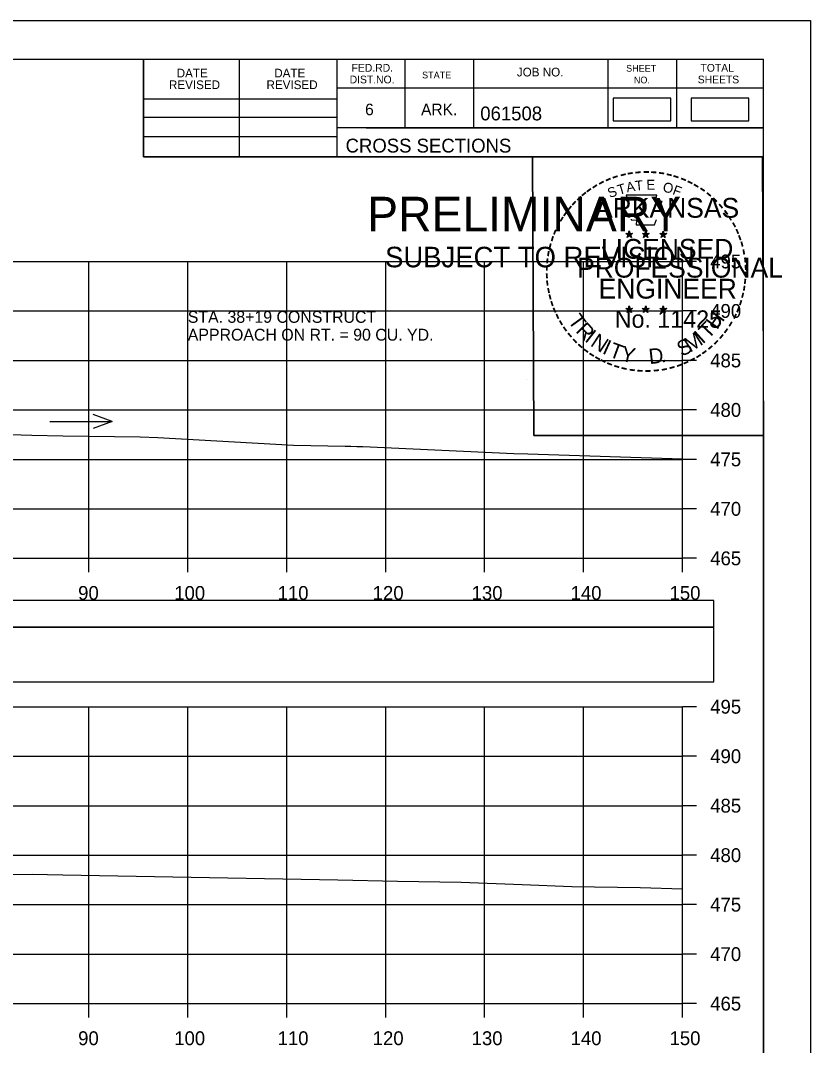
# Model space of a CAD drawing. Extents: x 1371057 to 1372761, y 380005 to 390517.
# Drawn here: x 1371644 to 1371723.8, y 381181.5 to 381285.1 of the extents above; entities that cross this region are included whole.
import ezdxf

# ---------------------------------------------------------------- set-up
doc = ezdxf.new("R2010")
doc.units = 0
for name, color, linetype in [('R_Axis', 7, 'Continuous'), ('R_Axis Annot', 7, 'Continuous'), ('R_Border', 7, 'Continuous'), ('R_Border PE', 7, 'Continuous'), ('R_Border Prem', 7, 'Continuous'), ('R_Detour', 7, 'Continuous'), ('R_Dimension', 7, 'Continuous'), ('R_Exist Surface', 7, 'Continuous'), ('R_Grid', 7, 'Continuous'), ('R_No Plot', 7, 'Continuous'), ('R_Water Annot', 7, 'Continuous')]:
    doc.layers.add(name, color=color, linetype=linetype)

msp = doc.modelspace()

# ---------------------------------------------------------------- linework, layer by layer
at = {"layer": 'R_Axis'}
for p, q in [((1371710.87, 381230.75), (1371710.87, 381260.75)), ((1371712.27, 381260.75), (1371710.87, 381260.75)), ((1371712.27, 381255.75), (1371710.87, 381255.75)), ((1371712.27, 381250.75), (1371710.87, 381250.75)), ((1371712.27, 381245.75), (1371710.87, 381245.75)), ((1371712.27, 381240.75), (1371710.87, 381240.75)), ((1371712.27, 381235.75), (1371710.87, 381235.75)), ((1371410.87, 381230.75), (1371710.87, 381230.75)), ((1371650.87, 381229.35), (1371650.87, 381230.75)), ((1371660.87, 381229.35), (1371660.87, 381230.75)), ((1371670.87, 381229.35), (1371670.87, 381230.75)), ((1371680.87, 381229.35), (1371680.87, 381230.75)), ((1371690.87, 381229.35), (1371690.87, 381230.75)), ((1371700.87, 381229.35), (1371700.87, 381230.75)), ((1371710.87, 381229.35), (1371710.87, 381230.75)), ((1371712.27, 381230.75), (1371710.87, 381230.75)), ((1371710.87, 381185.75), (1371710.87, 381215.75)), ((1371712.27, 381215.75), (1371710.87, 381215.75)), ((1371712.27, 381210.75), (1371710.87, 381210.75)), ((1371712.27, 381205.75), (1371710.87, 381205.75)), ((1371712.27, 381200.75), (1371710.87, 381200.75)), ((1371712.27, 381195.75), (1371710.87, 381195.75)), ((1371712.27, 381190.75), (1371710.87, 381190.75)), ((1371410.87, 381185.75), (1371710.87, 381185.75)), ((1371650.87, 381184.35), (1371650.87, 381185.75)), ((1371660.87, 381184.35), (1371660.87, 381185.75)), ((1371670.87, 381184.35), (1371670.87, 381185.75)), ((1371680.87, 381184.35), (1371680.87, 381185.75)), ((1371690.87, 381184.35), (1371690.87, 381185.75)), ((1371700.87, 381184.35), (1371700.87, 381185.75)), ((1371710.87, 381184.35), (1371710.87, 381185.75)), ((1371712.27, 381185.75), (1371710.87, 381185.75))]:
    msp.add_line(p, q, dxfattribs=at)
at = {"layer": 'R_Border'}
for p, q in [((1371402.87, 381281.21), (1371719.05, 381281.21)), ((1371656.41, 381271.33), (1371656.41, 381281.21)), ((1371666.09, 381271.33), (1371666.09, 381281.21)), ((1371675.95, 381281.21), (1371675.95, 381271.33)), ((1371682.79, 381281.21), (1371682.79, 381274.27)), ((1371689.73, 381281.21), (1371689.73, 381274.27)), ((1371703.31, 381281.21), (1371703.31, 381274.27)), ((1371710.25, 381281.21), (1371710.25, 381274.27)), ((1371719.05, 381075.75), (1371719.05, 381281.21)), ((1371719.05, 381278.27), (1371675.95, 381278.27)), ((1371719.05, 381278.29), (1371719.05, 381278.29)), ((1371656.41, 381277.19), (1371675.95, 381277.19)), ((1371656.41, 381275.33), (1371675.95, 381275.33)), ((1371719.05, 381274.27), (1371675.95, 381274.27)), ((1371678.91, 381274.27), (1371719.05, 381274.27)), ((1371656.41, 381273.39), (1371675.95, 381273.39)), ((1371719.05, 381271.33), (1371656.41, 381271.33))]:
    msp.add_line(p, q, dxfattribs=at)
at = {"layer": 'R_Border PE'}
for p, q in [((1371705.14, 381263.58), (1371705.49, 381263.47)), ((1371705.14, 381263.58), (1371705.39, 381263.54)), ((1371705.14, 381263.58), (1371705.37, 381263.46)), ((1371705.49, 381263.84), (1371705.45, 381263.59)), ((1371705.49, 381263.47), (1371705.49, 381263.84)), ((1371705.49, 381263.84), (1371705.54, 381263.59)), ((1371705.83, 381263.58), (1371705.49, 381263.47)), ((1371705.83, 381263.58), (1371705.55, 381263.54)), ((1371705.83, 381263.58), (1371705.63, 381263.48)), ((1371706.81, 381263.58), (1371707.16, 381263.47)), ((1371706.81, 381263.58), (1371707.06, 381263.54)), ((1371706.81, 381263.58), (1371707.04, 381263.46)), ((1371707.16, 381263.84), (1371707.12, 381263.59)), ((1371707.16, 381263.47), (1371707.16, 381263.84)), ((1371707.16, 381263.84), (1371707.21, 381263.59)), ((1371707.5, 381263.58), (1371707.16, 381263.47)), ((1371707.5, 381263.58), (1371707.22, 381263.54)), ((1371707.5, 381263.58), (1371707.3, 381263.48)), ((1371708.57, 381263.57), (1371708.92, 381263.46)), ((1371708.57, 381263.57), (1371708.82, 381263.53)), ((1371708.57, 381263.57), (1371708.81, 381263.45)), ((1371708.92, 381263.83), (1371708.88, 381263.57)), ((1371708.92, 381263.46), (1371708.92, 381263.83)), ((1371708.92, 381263.83), (1371708.97, 381263.58)), ((1371709.27, 381263.57), (1371708.92, 381263.46)), ((1371709.27, 381263.57), (1371708.98, 381263.52)), ((1371709.27, 381263.57), (1371709.06, 381263.47)), ((1371705.27, 381263.18), (1371705.49, 381263.47)), ((1371705.27, 381263.18), (1371705.4, 381263.42)), ((1371705.27, 381263.18), (1371705.48, 381263.39)), ((1371705.7, 381263.18), (1371705.48, 381263.39)), ((1371705.7, 381263.18), (1371705.49, 381263.47)), ((1371705.7, 381263.18), (1371705.56, 381263.47)), ((1371706.94, 381263.18), (1371707.16, 381263.47)), ((1371706.94, 381263.18), (1371707.07, 381263.42)), ((1371706.94, 381263.18), (1371707.15, 381263.39)), ((1371707.37, 381263.18), (1371707.15, 381263.39)), ((1371707.37, 381263.18), (1371707.16, 381263.47)), ((1371707.37, 381263.18), (1371707.23, 381263.47)), ((1371708.7, 381263.16), (1371708.92, 381263.46)), ((1371708.7, 381263.16), (1371708.83, 381263.41)), ((1371708.7, 381263.16), (1371708.92, 381263.38)), ((1371709.13, 381263.16), (1371708.92, 381263.46)), ((1371709.13, 381263.16), (1371708.92, 381263.38)), ((1371709.13, 381263.16), (1371709, 381263.46)), ((1371705.48, 381256.27), (1371705.44, 381256.01)), ((1371705.48, 381255.9), (1371705.48, 381256.27)), ((1371705.48, 381256.27), (1371705.53, 381256.02)), ((1371707.15, 381256.27), (1371707.11, 381256.01)), ((1371707.15, 381255.9), (1371707.15, 381256.27)), ((1371707.15, 381256.27), (1371707.2, 381256.02)), ((1371708.92, 381256.26), (1371708.88, 381256)), ((1371708.92, 381255.89), (1371708.92, 381256.26)), ((1371708.92, 381256.26), (1371708.97, 381256.01)), ((1371705.13, 381256.01), (1371705.48, 381255.9)), ((1371705.13, 381256.01), (1371705.39, 381255.97)), ((1371705.13, 381256.01), (1371705.37, 381255.89)), ((1371705.27, 381255.6), (1371705.48, 381255.9)), ((1371705.27, 381255.6), (1371705.39, 381255.85)), ((1371705.27, 381255.6), (1371705.48, 381255.82)), ((1371705.83, 381256.01), (1371705.48, 381255.9)), ((1371705.7, 381255.6), (1371705.48, 381255.9)), ((1371705.7, 381255.6), (1371705.48, 381255.82)), ((1371705.83, 381256.01), (1371705.54, 381255.96)), ((1371705.7, 381255.6), (1371705.56, 381255.89)), ((1371705.83, 381256.01), (1371705.63, 381255.91)), ((1371706.8, 381256.01), (1371707.15, 381255.9)), ((1371706.8, 381256.01), (1371707.06, 381255.97)), ((1371706.8, 381256.01), (1371707.04, 381255.89)), ((1371706.94, 381255.6), (1371707.15, 381255.9)), ((1371706.94, 381255.6), (1371707.06, 381255.85)), ((1371706.94, 381255.6), (1371707.15, 381255.82)), ((1371707.5, 381256.01), (1371707.15, 381255.9)), ((1371707.36, 381255.6), (1371707.15, 381255.9)), ((1371707.36, 381255.6), (1371707.15, 381255.82)), ((1371707.5, 381256.01), (1371707.21, 381255.96)), ((1371707.36, 381255.6), (1371707.23, 381255.89)), ((1371707.5, 381256.01), (1371707.29, 381255.91)), ((1371708.57, 381256), (1371708.92, 381255.89)), ((1371708.57, 381256), (1371708.82, 381255.96)), ((1371708.57, 381256), (1371708.81, 381255.88)), ((1371708.7, 381255.59), (1371708.92, 381255.89)), ((1371708.7, 381255.59), (1371708.83, 381255.84)), ((1371708.7, 381255.59), (1371708.92, 381255.81)), ((1371709.27, 381256), (1371708.92, 381255.89)), ((1371709.13, 381255.59), (1371708.92, 381255.89)), ((1371709.13, 381255.59), (1371708.92, 381255.81)), ((1371709.27, 381256), (1371708.98, 381255.95)), ((1371709.13, 381255.59), (1371708.99, 381255.88)), ((1371709.27, 381256), (1371709.06, 381255.9))]:
    msp.add_line(p, q, dxfattribs=at)
for points in [[(1371705.18, 381267.46), (1371705.45, 381266.64)], [(1371708.69, 381266.54), (1371708.83, 381266.82), (1371708.15, 381266.8), (1371708.29, 381267.46), (1371705.18, 381267.46)], [(1371705.67, 381265.04), (1371705.67, 381264.95), (1371706.23, 381264.93), (1371706.18, 381264.46), (1371708.05, 381264.46), (1371708.25, 381265)], [(1371705.49, 381263.84), (1371705.7, 381263.18), (1371705.14, 381263.58), (1371705.83, 381263.58), (1371705.27, 381263.18), (1371705.49, 381263.84)], [(1371707.16, 381263.84), (1371707.37, 381263.18), (1371706.81, 381263.58), (1371707.5, 381263.58), (1371706.94, 381263.18), (1371707.16, 381263.84)], [(1371708.92, 381263.83), (1371709.13, 381263.16), (1371708.57, 381263.57), (1371709.27, 381263.57), (1371708.7, 381263.16), (1371708.92, 381263.83)], [(1371705.48, 381256.27), (1371705.7, 381255.6), (1371705.13, 381256.01), (1371705.83, 381256.01), (1371705.27, 381255.6), (1371705.48, 381256.27)], [(1371707.15, 381256.27), (1371707.36, 381255.6), (1371706.8, 381256.01), (1371707.5, 381256.01), (1371706.94, 381255.6), (1371707.15, 381256.27)], [(1371708.92, 381256.26), (1371709.13, 381255.59), (1371708.57, 381256), (1371709.27, 381256), (1371708.7, 381255.59), (1371708.92, 381256.26)]]:
    msp.add_lwpolyline(points, dxfattribs=at)
for centre, radius in [((1371705.49, 381263.47), 0.172), ((1371705.49, 381263.47), 0.145), ((1371705.49, 381263.47), 0.116), ((1371705.49, 381263.47), 0.0991), ((1371705.49, 381263.47), 0.0747), ((1371705.49, 381263.47), 0.0495), ((1371705.49, 381263.47), 0.0296), ((1371707.16, 381263.47), 0.172), ((1371707.16, 381263.47), 0.145), ((1371707.16, 381263.47), 0.116), ((1371707.16, 381263.47), 0.0991), ((1371707.16, 381263.47), 0.0747), ((1371707.16, 381263.47), 0.0495), ((1371707.16, 381263.47), 0.0296), ((1371708.92, 381263.46), 0.172), ((1371708.92, 381263.46), 0.145), ((1371708.92, 381263.46), 0.116), ((1371708.92, 381263.46), 0.0991), ((1371708.92, 381263.46), 0.0747), ((1371708.92, 381263.46), 0.0495), ((1371708.92, 381263.46), 0.0296), ((1371705.48, 381255.9), 0.172), ((1371705.48, 381255.9), 0.145), ((1371705.48, 381255.9), 0.116), ((1371705.48, 381255.9), 0.0991), ((1371705.48, 381255.9), 0.0747), ((1371705.48, 381255.9), 0.0495), ((1371705.48, 381255.9), 0.0296), ((1371707.15, 381255.9), 0.172), ((1371707.15, 381255.9), 0.145), ((1371707.15, 381255.9), 0.116), ((1371707.15, 381255.9), 0.0991), ((1371707.15, 381255.9), 0.0747), ((1371707.15, 381255.9), 0.0495), ((1371707.15, 381255.9), 0.0296), ((1371708.92, 381255.89), 0.172), ((1371708.92, 381255.89), 0.145), ((1371708.92, 381255.89), 0.116), ((1371708.92, 381255.89), 0.0991), ((1371708.92, 381255.89), 0.0747), ((1371708.92, 381255.89), 0.0495), ((1371708.92, 381255.89), 0.0296)]:
    msp.add_circle(centre, radius, dxfattribs=at)
at = {"layer": 'R_Detour'}
msp.add_lwpolyline([(1371407.72, 381223.8), (1371714.03, 381223.8), (1371714.03, 381226.5), (1371407.72, 381226.5)], close=True, dxfattribs=at)
at = {"layer": 'R_Dimension'}
for points in [[(1371703.87, 381274.96), (1371709.7, 381274.96), (1371709.7, 381277.27), (1371703.87, 381277.27)], [(1371711.74, 381274.96), (1371717.57, 381274.96), (1371717.57, 381277.27), (1371711.74, 381277.27)], [(1371407.72, 381218.27), (1371714.03, 381218.27), (1371714.03, 381223.8), (1371407.72, 381223.8)]]:
    msp.add_lwpolyline(points, close=True, dxfattribs=at)
at = {"layer": 'R_Exist Surface'}
for points in [[(1371641.92, 381243.3), (1371645.1, 381243.19), (1371648.24, 381243.12), (1371656.05, 381243.04), (1371657.85, 381242.96), (1371671.57, 381242.18), (1371676.78, 381242.09), (1371677.35, 381242.07), (1371677.96, 381242.06), (1371678.55, 381242.04), (1371693.82, 381241.34), (1371695.24, 381241.32), (1371710.87, 381240.82)], [(1371634.78, 381198.78), (1371645.15, 381198.83), (1371648.24, 381198.76), (1371676.03, 381198.27), (1371682.05, 381198.12), (1371688.49, 381198.03), (1371694.66, 381197.8), (1371699.68, 381197.57), (1371706.6, 381197.49), (1371710.87, 381197.36)]]:
    msp.add_lwpolyline(points, dxfattribs=at)
at = {"layer": 'R_Grid'}
for p, q in [((1371410.87, 381260.75), (1371710.87, 381260.75)), ((1371650.87, 381230.75), (1371650.87, 381260.75)), ((1371660.87, 381230.75), (1371660.87, 381260.75)), ((1371670.87, 381230.75), (1371670.87, 381260.75)), ((1371680.87, 381230.75), (1371680.87, 381260.75)), ((1371690.87, 381230.75), (1371690.87, 381260.75)), ((1371700.87, 381230.75), (1371700.87, 381260.75)), ((1371710.87, 381230.75), (1371710.87, 381260.75)), ((1371410.87, 381255.75), (1371710.87, 381255.75)), ((1371410.87, 381250.75), (1371710.87, 381250.75)), ((1371410.87, 381245.75), (1371710.87, 381245.75)), ((1371410.87, 381240.75), (1371710.87, 381240.75)), ((1371410.87, 381235.75), (1371710.87, 381235.75)), ((1371410.87, 381230.75), (1371710.87, 381230.75)), ((1371410.87, 381215.75), (1371710.87, 381215.75)), ((1371650.87, 381185.75), (1371650.87, 381215.75)), ((1371660.87, 381185.75), (1371660.87, 381215.75)), ((1371670.87, 381185.75), (1371670.87, 381215.75)), ((1371680.87, 381185.75), (1371680.87, 381215.75)), ((1371690.87, 381185.75), (1371690.87, 381215.75)), ((1371700.87, 381185.75), (1371700.87, 381215.75)), ((1371710.87, 381185.75), (1371710.87, 381215.75)), ((1371410.87, 381210.75), (1371710.87, 381210.75)), ((1371410.87, 381205.75), (1371710.87, 381205.75)), ((1371410.87, 381200.75), (1371710.87, 381200.75)), ((1371410.87, 381195.75), (1371710.87, 381195.75)), ((1371410.87, 381190.75), (1371710.87, 381190.75)), ((1371410.87, 381185.75), (1371710.87, 381185.75))]:
    msp.add_line(p, q, dxfattribs=at)
at = {"layer": 'R_No Plot'}
for p, q in [((1371390.47, 381285.1), (1371723.8, 381285.1)), ((1371695.09, 381248.87), (1371695.09, 381248.87))]:
    msp.add_line(p, q, dxfattribs=at)
for points in [[(1371390.46, 381285.1), (1371723.8, 381285.1), (1371723.8, 381071.77), (1371390.46, 381071.77)], [(1371636.79, 381281.21), (1371656.41, 381281.21), (1371656.41, 381271.33), (1371672.52, 381271.33), (1371695.72, 381271.33), (1371695.84, 381243.17), (1371719.05, 381243.17), (1371719.05, 381075.75), (1371402.87, 381075.75), (1371402.87, 381281.21)], [(1371695.72, 381271.33), (1371718.93, 381271.33), (1371719.05, 381243.17), (1371695.84, 381243.17)]]:
    msp.add_lwpolyline(points, close=True, dxfattribs=at)
at = {"layer": 'R_Water Annot'}
for p, q in [((1371653.22, 381244.57), (1371651.3, 381245.27)), ((1371646.94, 381244.57), (1371653.22, 381244.57)), ((1371653.22, 381244.57), (1371651.3, 381243.87))]:
    msp.add_line(p, q, dxfattribs=at)

# ---------------------------------------------------------------- texts
at = {"layer": 'R_Axis Annot'}
for s, p in [('495', (1371713.67, 381260.05)), ('490', (1371713.67, 381255.05)), ('485', (1371713.67, 381250.05)), ('480', (1371713.67, 381245.05)), ('475', (1371713.67, 381240.05)), ('470', (1371713.67, 381235.05)), ('465', (1371713.67, 381230.05)), ('90', (1371649.79, 381226.55)), ('100', (1371659.5, 381226.55)), ('110', (1371669.95, 381226.55)), ('120', (1371679.56, 381226.55)), ('130', (1371689.56, 381226.55)), ('140', (1371699.56, 381226.55)), ('150', (1371709.56, 381226.55)), ('495', (1371713.67, 381215.05)), ('490', (1371713.67, 381210.05)), ('485', (1371713.67, 381205.05)), ('480', (1371713.67, 381200.05)), ('475', (1371713.67, 381195.05)), ('470', (1371713.67, 381190.05)), ('465', (1371713.67, 381185.05)), ('90', (1371649.79, 381181.55)), ('100', (1371659.5, 381181.55)), ('110', (1371669.95, 381181.55)), ('120', (1371679.56, 381181.55)), ('130', (1371689.56, 381181.55)), ('140', (1371699.56, 381181.55)), ('150', (1371709.56, 381181.55))]:
    msp.add_text(s, height=1.4, dxfattribs=at).set_placement(p)
at = {"layer": 'R_Border'}
for s, height, p in [('DATE', 0.879, (1371659.75, 381279.35)), ('DATE', 0.879, (1371669.61, 381279.35)), ('FED.RD.', 0.782, (1371677.43, 381279.93)), ('JOB NO.', 0.879, (1371694.13, 381279.45)), ('SHEET', 0.684, (1371705.17, 381279.93)), ('TOTAL', 0.782, (1371712.69, 381279.93)), ('REVISED', 0.879, (1371658.97, 381278.17)), ('REVISED', 0.879, (1371668.83, 381278.17)), ('DIST.NO.', 0.782, (1371677.23, 381278.75)), ('STATE', 0.684, (1371684.55, 381279.25)), ('NO.', 0.684, (1371705.95, 381278.75)), ('SHEETS', 0.782, (1371712.41, 381278.75)), ('6', 1.17, (1371678.79, 381275.53)), ('ARK.', 1.172, (1371684.45, 381275.53)), ('061508', 1.4, (1371690.43, 381275.01)), ('CROSS SECTIONS', 1.4, (1371676.82, 381271.76))]:
    msp.add_text(s, height=height, rotation=360, dxfattribs=at).set_placement(p)
at = {"layer": 'R_Border PE'}
for s, height, rotation, p in [('-', 1.6, 10.2193, (1371705.35, 381268.99)), ('-', 1.6, 5.8968, (1371706.08, 381269.1)), ('-', 1.6, 0.1862, (1371706.86, 381269.17)), ('-', 1.6, 357.743, (1371707.58, 381269.16)), ('-', 1.6, 352.1617, (1371708.32, 381269.11)), ('-', 1.6, 28.7918, (1371702.66, 381268)), ('-', 1.6, 24.3072, (1371703.29, 381268.32)), ('-', 1.6, 19.1761, (1371703.93, 381268.59)), ('-', 1.6, 13.6301, (1371704.68, 381268.83)), ('A', 1, 11.2132, (1371705.27, 381267.72)), ('T', 1, 6.0228, (1371706.12, 381267.89)), ('E', 1, 0.8323, (1371707.23, 381268)), ('O', 1, 350.4515, (1371708.83, 381267.79)), ('-', 1.6, 347.2049, (1371709.04, 381268.99)), ('-', 1.6, 342.3362, (1371709.68, 381268.84)), ('-', 1.6, 337.8551, (1371710.41, 381268.61)), ('-', 1.6, 334.1211, (1371711.04, 381268.34)), ('-', 1.6, 38.9507, (1371701.01, 381266.86)), ('-', 1.6, 36.2317, (1371701.48, 381267.24)), ('-', 1.6, 34.0636, (1371702.06, 381267.63)), ('S', 1, 21.594, (1371703.53, 381267.14)), ('T', 1, 16.4036, (1371704.45, 381267.47)), ('F', 1, 340.0707, (1371709.79, 381267.56)), ('-', 1.6, 329.6409, (1371711.62, 381268.06)), ('-', 1.6, 325.8627, (1371712.26, 381267.7)), ('-', 1.6, 320.5297, (1371712.87, 381267.27)), ('-', 1.6, 48.423, (1371700.13, 381265.97)), ('-', 1.6, 42.9622, (1371700.58, 381266.44)), ('ARKANSAS', 2, 360, (1371702.03, 381265.17)), ('-', 1.6, 315.5786, (1371713.47, 381266.78)), ('-', 1.6, 309.8797, (1371714.04, 381266.23)), ('-', 1.6, 54.2325, (1371699.31, 381264.91)), ('-', 1.6, 50.6142, (1371699.72, 381265.48)), ('-', 1.6, 306.6522, (1371714.57, 381265.63)), ('-', 1.6, 62.8713, (1371698.67, 381263.77)), ('-', 1.6, 58.0706, (1371698.99, 381264.39)), ('-', 1.4, 303.6753, (1371715.05, 381265.06)), ('-', 1.6, 299.6684, (1371715.37, 381264.46)), ('-', 1.6, 67.7743, (1371698.41, 381263.16)), ('-', 1.6, 294.6628, (1371715.7, 381263.85)), ('-', 1.6, 75.461, (1371698, 381261.82)), ('-', 1.6, 72.3945, (1371698.2, 381262.53)), ('LICENSED', 2, 360, (1371702.63, 381261.03)), ('DWB', 0.01, 360, (1371705.47, 381263.47)), ('DWB', 0.01, 360, (1371707.14, 381263.47)), ('DWB', 0.01, 360, (1371708.91, 381263.46)), ('-', 1.6, 290.5728, (1371715.95, 381263.27)), ('-', 1.6, 285.1233, (1371716.19, 381262.69)), ('-', 1.6, 81.2013, (1371697.87, 381261.1)), ('-', 1.6, 280.5493, (1371716.39, 381261.95)), ('-', 1.6, 85.1863, (1371697.79, 381260.41)), ('PROFESSIONAL', 2, 360, (1371700.21, 381259.12)), ('-', 1.6, 276.5962, (1371716.55, 381261.18)), ('-', 1.6, 274.3301, (1371716.61, 381260.46)), ('-', 1.6, 94.1959, (1371697.8, 381258.99)), ('-', 1.6, 89.0622, (1371697.77, 381259.71)), ('-', 1.6, 269.9407, (1371716.64, 381259.82)), ('-', 1.6, 98.9479, (1371697.87, 381258.32)), ('ENGINEER', 2, 360, (1371702.39, 381257)), ('-', 1.6, 260.9953, (1371716.55, 381258.5)), ('-', 1.6, 263.5172, (1371716.62, 381259.16)), ('-', 1.6, 101.7149, (1371698.01, 381257.59)), ('-', 1.6, 105.4578, (1371698.17, 381256.99)), ('-', 1.6, 255.7626, (1371716.44, 381257.83)), ('-', 1.6, 109.0874, (1371698.38, 381256.36)), ('-', 1.6, 252.8681, (1371716.26, 381257.11)), ('-', 1.6, 114.0643, (1371698.64, 381255.76)), ('-', 1.6, 115.7289, (1371698.94, 381255.15)), ('T', 1.54, 306.0406, (1371699.24, 381254.74)), ('No. 11425', 1.757, 360, (1371704.02, 381254.05)), ('DWB', 0.01, 360, (1371705.47, 381255.9)), ('DWB', 0.01, 360, (1371707.14, 381255.9)), ('DWB', 0.01, 360, (1371708.91, 381255.89)), ('H', 1.54, 54.6088, (1371714.36, 381253.77)), ('-', 1.6, 244.6197, (1371715.78, 381255.8)), ('-', 1.6, 247.8887, (1371716.04, 381256.43)), ('-', 1.6, 120.4471, (1371699.3, 381254.56)), ('-', 1.6, 125.8934, (1371699.7, 381254)), ('R', 1.54, 314.005, (1371700, 381253.69)), ('T', 1.54, 46.6444, (1371713.47, 381252.83)), ('-', 1.6, 239.0712, (1371715.38, 381255.05)), ('-', 1.6, 130.7181, (1371700.17, 381253.45)), ('I', 1.54, 321.9694, (1371700.9, 381252.76)), ('N', 1.54, 326.5002, (1371701.47, 381252.29)), ('M', 1.54, 32.6563, (1371711.63, 381251.51)), ('I', 1.54, 42.1136, (1371712.91, 381252.35)), ('-', 1.6, 231.2538, (1371714.55, 381253.83)), ('-', 1.6, 233.8452, (1371714.98, 381254.4)), ('-', 1.6, 134.2238, (1371700.68, 381252.9)), ('-', 1.6, 138.9338, (1371701.21, 381252.44)), ('I', 1.54, 335.3603, (1371702.68, 381251.5)), ('T', 1.54, 339.8912, (1371703.34, 381251.17)), ('Y', 1.54, 347.8556, (1371704.56, 381250.73)), ('S', 1.54, 26.9312, (1371710.79, 381251.1)), ('-', 1.6, 221.0851, (1371713.55, 381252.76)), ('-', 1.6, 225.7653, (1371714.07, 381253.27)), ('-', 1.6, 144.6463, (1371701.76, 381252.03)), ('-', 1.6, 148.0898, (1371702.32, 381251.66)), ('-', 1.6, 151.5704, (1371702.9, 381251.34)), ('D', 1.54, 6.3969, (1371707.54, 381250.37)), ('-', 1.6, 212.2491, (1371712.47, 381251.9)), ('-', 1.6, 215.7363, (1371713, 381252.29)), ('-', 1.6, 154.6002, (1371703.43, 381251.09)), ('-', 1.6, 158.5612, (1371704.05, 381250.84)), ('-', 1.6, 162.7983, (1371704.74, 381250.62)), ('-', 1.6, 167.5555, (1371705.45, 381250.46)), ('.', 1.54, 13.7642, (1371708.74, 381250.5)), ('-', 1.6, 195.4743, (1371709.99, 381250.72)), ('-', 1.6, 200.7184, (1371710.67, 381250.96)), ('-', 1.6, 204.2516, (1371711.29, 381251.24)), ('-', 1.6, 207.3568, (1371711.91, 381251.56)), ('-', 1.6, 173.1155, (1371706.22, 381250.35)), ('-', 1.6, 176.5183, (1371706.97, 381250.3)), ('-', 1.6, 181.5918, (1371707.72, 381250.31)), ('-', 1.6, 185.8167, (1371708.52, 381250.39)), ('-', 1.6, 191.2858, (1371709.26, 381250.52))]:
    msp.add_text(s, height=height, rotation=rotation, dxfattribs=at).set_placement(p)
at = {"layer": 'R_Border Prem'}
for s, height, p in [('PRELIMINARY', 3.5, (1371679, 381263.79)), ('DWB', 0.01, (1371679.75, 381265.64)), ('SUBJECT TO REVISION', 2.0751, (1371680.81, 381260.16))]:
    msp.add_text(s, height=height, rotation=360, dxfattribs=at).set_placement(p)
at = {"layer": 'R_Water Annot'}
for s, p in [('STA. 38+19 CONSTRUCT', (1371660.87, 381254.55)), ('APPROACH ON RT. = 90 CU. YD.', (1371660.87, 381252.75))]:
    msp.add_text(s, height=1.2, dxfattribs=at).set_placement(p)

doc.saveas('drawing.dxf')
